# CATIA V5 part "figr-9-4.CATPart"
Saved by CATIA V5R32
Part number: Part1
Bounding box of the stored display mesh (mm): x -71.324 to 69.61, y -139.735 to 0, z 0 to 45
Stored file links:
  D:\PROJECTS\Project 2022\CATIA V5 6R 2022\Resources\Part Files\c09_catia_v5_6r2022_prt\c09_catia_v5_6r2022_prt\figr-9-4.CATPart
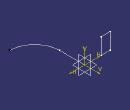
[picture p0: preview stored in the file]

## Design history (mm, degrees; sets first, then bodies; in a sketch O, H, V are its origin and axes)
Body1 (main body)
  Sketch1 on xy-plane, origin (0, 0, 0), H (1, 0, 0), V (0, 1, 0)
    line L1 (0, 0) -> (0, -70.1255)
    arc A1 centre (69.6095, -70.1255) radius 69.6095 from (0, -70.1255) to (69.6095, -139.7351) ccw
    vertical: L1 V
    tangency: A1 L1
  Sketch2 on zx-plane, origin (0, 0, 0), H (-1, 0, 0), V (0, 0, 1)
    point P1 (46.3244, 0)
    line L1 (46.3244, 0) -> (71.3244, 0)
    line L2 (71.3244, 0) -> (71.3244, 45)
    line L3 (71.3244, 45) -> (46.3244, 45)
    line L4 (46.3244, 45) -> (46.3244, 0)
    length L3 = 25
    length L2 = 45
    coincidence: P1 H
    horizontal: L1 H, L3 H
    vertical: L2 V, L4 V
  Rib1: profile Sketch2, centre curve Sketch1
